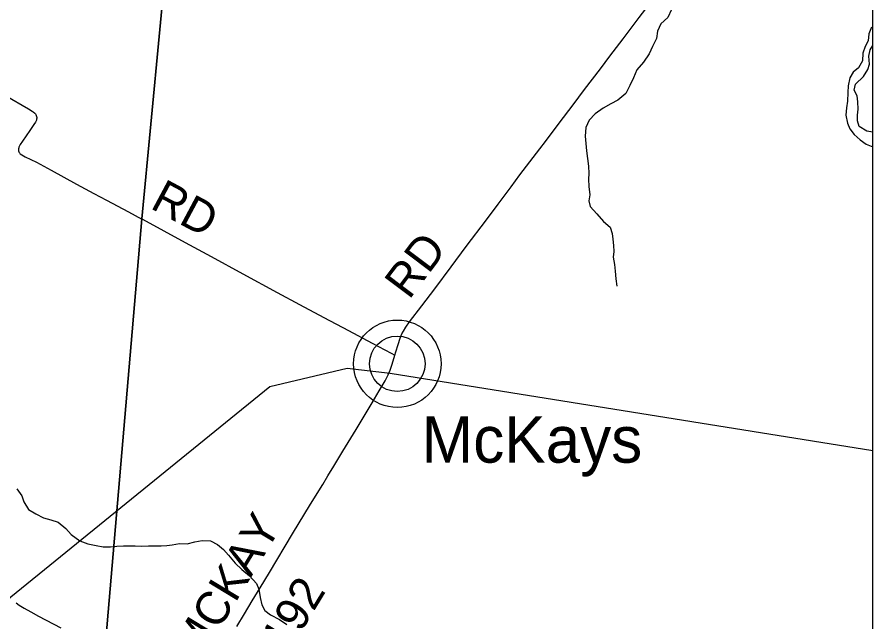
# Model space of a CAD drawing. Extents: x -1.4 to 35.4, y 0 to 22.
# Drawn here: x 7.544 to 9, y 16.946 to 17.975 of the extents above; entities that cross this region are included whole.
import ezdxf

# ---------------------------------------------------------------- set-up
doc = ezdxf.new("R2010")
doc.units = 0
for name, color, linetype in [('Default', 7, 'Continuous'), ('GM_X_Major_River', 7, 'Continuous'), ('GM_X_Minor_River', 7, 'Continuous'), ('GM_X_Rail_Line', 7, 'Continuous'), ('GM_X_Township_Road', 7, 'Continuous'), ('GM_X_Township_Road_Text', 7, 'Continuous'), ('GM_X_Unincorporated', 7, 'Continuous'), ('GM_X_Unincorporated_Location', 7, 'Continuous'), ('GM_X_Unincorporated_Text', 7, 'Continuous'), ('SH_Border', 7, 'Continuous'), ('SH_Cut_Line', 7, 'Continuous')]:
    doc.layers.add(name, color=color, linetype=linetype)

msp = doc.modelspace()

# ---------------------------------------------------------------- linework, layer by layer
at = {"layer": 'Default'}
msp.add_lwpolyline([(7.693, 16.8959), (7.7561, 17.6322), (7.8789, 18.9217), (7.8947, 19.0723), (6.8306, 19.1588), (5.7921, 19.2341), (4.2528, 19.417), (3.4459, 19.4989), (3.4296, 19.5001), (2.9037, 19.5459), (2.7894, 18.3098), (2.7365, 17.7956), (2.7172, 17.4718), (2.7109, 17.4025), (2.7066, 17.3545), (2.7033, 17.3163), (2.7006, 17.2849), (2.6906, 17.1666), (2.6843, 17.0961), (2.6688, 16.9164)], dxfattribs=at)
msp.add_lwpolyline([(9, 15.5849), (9, 18.9633), (8.143, 19.049), (7.8947, 19.0723), (7.8789, 18.9217), (7.7561, 17.6322), (7.693, 16.8959), (7.6066, 15.899), (7.5875, 15.692), (8.1578, 15.6562), (8.256, 15.6481), (8.9658, 15.5879)], close=True, dxfattribs=at)
at = {"layer": 'GM_X_Major_River'}
for points in [[(8.9974, 17.9579), (8.9932, 17.9466), (8.9917, 17.9348), (8.9871, 17.9253), (8.9829, 17.914), (8.9825, 17.9011), (8.9757, 17.8889), (8.9662, 17.8814), (8.9609, 17.8719), (8.9582, 17.8582), (8.9574, 17.8468), (8.9566, 17.8324), (8.9551, 17.8207), (8.954, 17.8082), (8.9566, 17.7949), (8.9607, 17.785), (8.9679, 17.7755), (8.9785, 17.7664), (8.9887, 17.7592), (8.9997, 17.7546), (9, 17.7545)], [(9, 17.7794), (8.9895, 17.7812), (8.9767, 17.7888), (8.9736, 17.7986), (8.974, 17.8085), (8.9748, 17.8184), (8.9745, 17.8309), (8.973, 17.8411), (8.9684, 17.851), (8.9707, 17.8609), (8.984, 17.8741), (8.9912, 17.8859), (8.9943, 17.8954), (8.9931, 17.909), (8.9951, 17.9193), (9, 17.9271)]]:
    msp.add_lwpolyline(points, dxfattribs=at)
at = {"layer": 'GM_X_Minor_River'}
for points in [[(8.6572, 17.9884), (8.6509, 17.9748), (8.639, 17.9636), (8.6338, 17.9516), (8.6317, 17.9391), (8.625, 17.9255), (8.6195, 17.9127), (8.6098, 17.8988), (8.5982, 17.8857), (8.593, 17.8721), (8.5863, 17.8589), (8.5796, 17.8453), (8.5662, 17.8341), (8.5539, 17.8275), (8.5412, 17.8205), (8.5274, 17.8105), (8.5174, 17.7996), (8.5118, 17.7872), (8.5104, 17.7727), (8.5118, 17.7602), (8.5127, 17.7476), (8.5147, 17.7347), (8.5164, 17.7214), (8.5166, 17.7092), (8.5164, 17.6997), (8.5169, 17.6868), (8.5182, 17.6727), (8.5165, 17.6625), (8.519, 17.653), (8.5302, 17.6407), (8.5417, 17.6276), (8.5529, 17.6175), (8.5562, 17.6072), (8.5575, 17.5973), (8.5585, 17.5867), (8.5594, 17.5764), (8.5581, 17.5669), (8.5606, 17.5543), (8.5615, 17.5429), (8.5628, 17.53), (8.5641, 17.5175)], [(7.5435, 17.1726), (7.552, 17.1607), (7.5552, 17.15), (7.5636, 17.1373), (7.576, 17.1298), (7.5892, 17.1231), (7.6016, 17.1198), (7.6141, 17.1158), (7.6268, 17.1049), (7.6361, 17.0945), (7.6507, 17.0839), (7.6646, 17.0787), (7.6786, 17.0758), (7.6903, 17.0736), (7.7029, 17.0738), (7.7139, 17.0747), (7.7249, 17.0752), (7.7344, 17.0754), (7.7447, 17.0752), (7.7553, 17.075), (7.7674, 17.0755), (7.7769, 17.0753), (7.7891, 17.0755), (7.7986, 17.0761), (7.8081, 17.077), (7.8203, 17.0794), (7.8336, 17.0788), (7.8465, 17.0819), (7.8591, 17.0847), (7.8728, 17.0841), (7.8848, 17.0778), (7.8953, 17.0692), (7.9038, 17.0595), (7.9149, 17.046), (7.9261, 17.0348), (7.9392, 17.0243), (7.9511, 17.0115), (7.9554, 17.0015), (7.9574, 16.9874), (7.9602, 16.9749), (7.9657, 16.9653), (7.9754, 16.9582), (7.9905, 16.95), (8.0028, 16.9417)]]:
    msp.add_lwpolyline(points, dxfattribs=at)
at = {"layer": 'GM_X_Rail_Line'}
msp.add_lwpolyline([(9, 17.2368), (8.179, 17.3686), (8.1053, 17.377), (7.9738, 17.3461), (7.5333, 16.988), (6.7907, 16.343), (6.0366, 15.6863)], dxfattribs=at)
at = {"layer": 'GM_X_Township_Road'}
for points in [[(8.1867, 17.4001), (8.1883, 17.4055), (8.1921, 17.4183), (8.1956, 17.4288), (8.1988, 17.4361), (8.2013, 17.441), (8.2052, 17.4473), (8.2117, 17.4564), (8.2324, 17.4836), (8.2545, 17.5128), (8.2823, 17.5502), (8.3083, 17.5851), (8.3424, 17.6302), (8.3624, 17.6571), (8.3844, 17.6864), (8.3995, 17.7066), (8.4333, 17.7513), (8.443, 17.7638), (8.4665, 17.7947), (8.4898, 17.8258), (8.5094, 17.8518), (8.5364, 17.8874), (8.5526, 17.9087), (8.5751, 17.9384), (8.5886, 17.9563), (8.6025, 17.9745), (8.6194, 17.9968)], [(7.5176, 17.8456), (7.5526, 17.8252), (7.5633, 17.8189), (7.5694, 17.815), (7.5712, 17.8138), (7.5742, 17.8116), (7.5751, 17.8106), (7.5759, 17.8094), (7.5765, 17.8077), (7.5769, 17.8063), (7.5773, 17.8046), (7.5773, 17.8031), (7.5772, 17.8015), (7.5768, 17.7999), (7.5753, 17.7967), (7.5726, 17.7924), (7.5655, 17.7821), (7.553, 17.7643), (7.5495, 17.7586), (7.5482, 17.7564), (7.5471, 17.754), (7.5467, 17.7526), (7.5464, 17.751), (7.5463, 17.7492), (7.5465, 17.7474), (7.5469, 17.7462), (7.5475, 17.7451), (7.5484, 17.7438), (7.5494, 17.7428), (7.5523, 17.7407), (7.5577, 17.7377), (7.5768, 17.7281), (7.602, 17.7147), (7.645, 17.6908), (7.6745, 17.6749), (7.6959, 17.6636), (7.7333, 17.6438), (7.7563, 17.6316), (7.7572, 17.6312)], [(7.7572, 17.6312), (7.8301, 17.5917), (7.8743, 17.5676), (7.9283, 17.5382), (7.9863, 17.5068), (8.0246, 17.4863), (8.0656, 17.4641), (8.1079, 17.4416), (8.148, 17.4205), (8.1804, 17.4034), (8.1867, 17.4001)], [(7.9178, 16.9381), (7.931, 16.9598), (7.9441, 16.9816), (7.9575, 17.004), (7.9734, 17.03), (8.0128, 17.0955), (8.0434, 17.146), (8.064, 17.18), (8.0728, 17.1943), (8.0828, 17.2107), (8.0981, 17.2363), (8.1209, 17.2734), (8.1481, 17.3187), (8.1602, 17.3389), (8.1701, 17.3562), (8.1752, 17.3662), (8.1787, 17.3742), (8.1817, 17.3831), (8.1839, 17.3905), (8.1867, 17.4001)], [(7.5422, 16.9782), (7.5478, 16.9742), (7.5558, 16.9693), (7.5672, 16.9628), (7.5803, 16.9557), (7.6183, 16.9358)]]:
    msp.add_lwpolyline(points, dxfattribs=at)
at = {"layer": 'GM_X_Unincorporated'}
for radius in [0.0744, 0.0472]:
    msp.add_circle((8.1909, 17.3852), radius, dxfattribs=at)
at = {"layer": 'GM_X_Unincorporated_Location'}
msp.add_line((8.1909, 17.3852), (8.1909, 17.3852), dxfattribs=at)
at = {"layer": 'SH_Border'}
msp.add_lwpolyline([(9, 19.8546), (2.2, 19.8546), (2.2, 13.0546), (9, 13.0546)], close=True, dxfattribs=at)
at = {"layer": 'SH_Cut_Line'}
msp.add_lwpolyline([(9, 13.0546), (9, 18.9633), (8.143, 19.049), (7.8947, 19.0723), (6.8306, 19.1588), (5.7921, 19.2341), (4.2528, 19.417), (3.4459, 19.4989), (3.4296, 19.5001), (2.9037, 19.5459), (2.7894, 18.3098), (2.7365, 17.7956), (2.7172, 17.4718), (2.7109, 17.4025), (2.7066, 17.3545), (2.7033, 17.3163), (2.7006, 17.2849), (2.6906, 17.1666), (2.6843, 17.0961), (2.6688, 16.9164)], dxfattribs=at)

# ---------------------------------------------------------------- texts
at = {"layer": 'GM_X_Township_Road_Text'}
for s, rotation, p in [('RD', 331.8923, (7.7686, 17.6508)), ('RD', 53.0286, (8.2109, 17.4929)), ('MCKAY', 58.7254, (7.8539, 16.8762)), ('T-192', 58.7039, (7.9672, 16.8291))]:
    msp.add_text(s, height=0.05682, rotation=rotation, dxfattribs=at).set_placement(p)
at = {"layer": 'GM_X_Unincorporated_Text'}
msp.add_text('McKays', height=0.07898, rotation=0, dxfattribs=at).set_placement((8.232, 17.2169))

doc.saveas('drawing.dxf')
